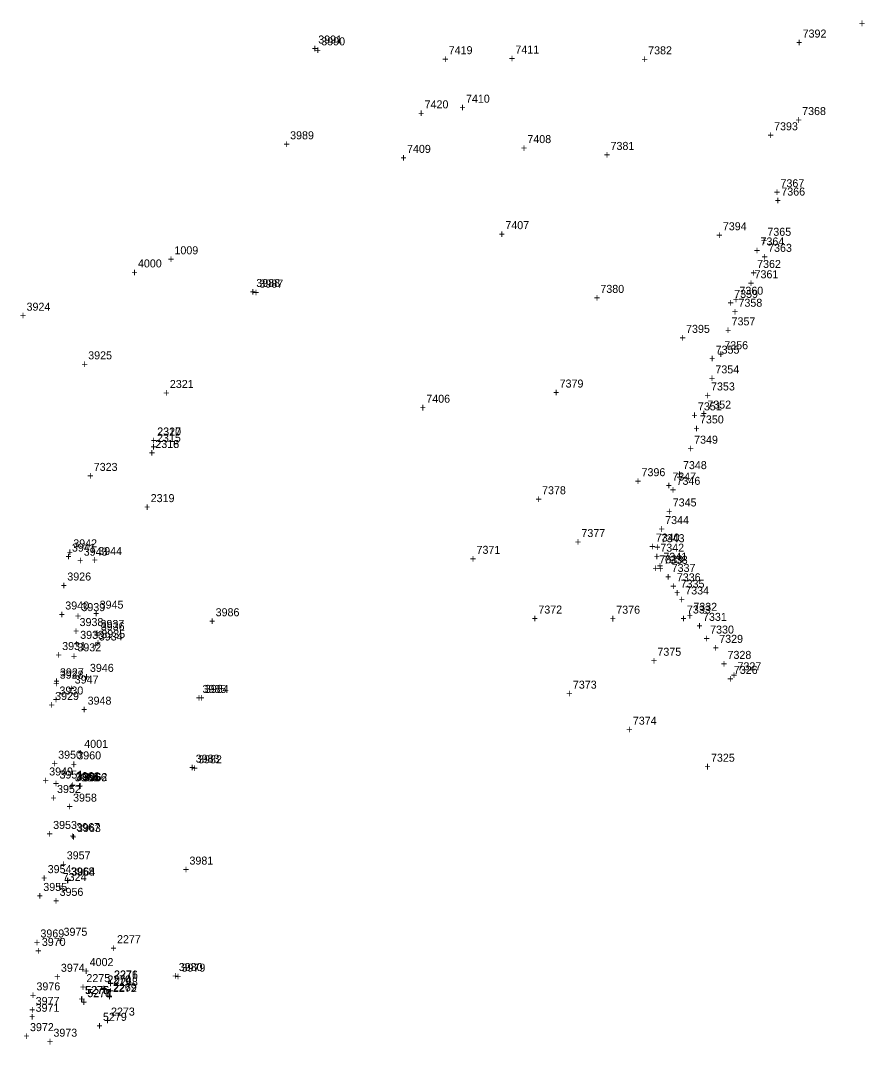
# Model space of a CAD drawing. Extents: x 1136220 to 1137808, y 528804 to 531215.
# Drawn here: x 1137418.6 to 1137682.5, y 530575 to 530894.9 of the extents above; entities that cross this region are included whole.
import ezdxf

# ---------------------------------------------------------------- set-up
doc = ezdxf.new("R2010")
doc.units = 0
for name, color, linetype in [('S_Buildings_SillElevation', 7, 'Continuous'), ('S_Drainage_CB', 7, 'Continuous'), ('S_Drainage_Culvert_Top', 7, 'Continuous'), ('S_Drainage_Invert', 7, 'Continuous'), ('S_Drainage_Sump', 7, 'Continuous'), ('S_Ground_Elevation', 7, 'Continuous'), ('S_Ground_SpotElevation', 7, 'Continuous'), ('S_Property_IronPipeFound', 7, 'Continuous'), ('S_Property_RockBoulder', 7, 'Continuous'), ('S_RetWall_Top', 7, 'Continuous'), ('S_Roadway_Monument', 7, 'Continuous'), ('S_Utilities_UG_Sanitary_MH', 7, 'Continuous'), ('S_Utilities_UG_Water_Line', 7, 'Continuous'), ('S_Utilities_UG_Water_Shutoff', 7, 'Continuous')]:
    doc.layers.add(name, color=color, linetype=linetype)

msp = doc.modelspace()

# ---------------------------------------------------------------- texts
at = {"layer": 'S_Buildings_SillElevation'}
for s, p in [('3924', (1137420.51, 530804.24)), ('+', (1137418.45, 530801.49)), ('3925', (1137439.79, 530789.05)), ('+', (1137437.72, 530786.3)), ('3926', (1137433.26, 530719.94)), ('+', (1137431.2, 530717.19)), ('3928', (1137430.89, 530689.27)), ('3927', (1137430.95, 530690.02)), ('+', (1137428.83, 530686.52)), ('+', (1137428.89, 530687.27)), ('3949', (1137427.59, 530659.04)), ('+', (1137425.53, 530656.29)), ('3976', (1137423.61, 530591.89)), ('+', (1137421.55, 530589.14)), ('3977', (1137423.37, 530587.34)), ('+', (1137421.31, 530584.59))]:
    msp.add_text(s, height=2.5, dxfattribs=at).set_placement(p)
at = {"layer": 'S_Drainage_CB'}
for s, p in [('5275', (1137438.78, 530590.73)), ('+', (1137436.72, 530587.98))]:
    msp.add_text(s, height=2.5, dxfattribs=at).set_placement(p)
at = {"layer": 'S_Drainage_Culvert_Top'}
for s, p in [('2321', (1137465.32, 530780.1)), ('+', (1137463.26, 530777.35)), ('2320', (1137461.37, 530765.23)), ('+', (1137459.31, 530762.48)), ('2318', (1137460.8, 530761.36)), ('+', (1137458.74, 530758.61)), ('2319', (1137459.32, 530744.44)), ('+', (1137457.26, 530741.69)), ('2277', (1137448.8, 530606.64)), ('+', (1137446.74, 530603.89)), ('2275', (1137439.22, 530594.47)), ('2274', (1137445.83, 530594.04)), ('2276', (1137447.9, 530595.56)), ('+', (1137437.16, 530591.72)), ('5278', (1137439.5, 530589.77)), ('+', (1137443.77, 530591.29)), ('+', (1137445.84, 530592.81)), ('2272', (1137447.52, 530591.36)), ('+', (1137437.44, 530587.02)), ('+', (1137445.45, 530588.62)), ('2273', (1137446.92, 530584.02)), ('5279', (1137444.41, 530582.38)), ('+', (1137444.86, 530581.27)), ('+', (1137442.35, 530579.63))]:
    msp.add_text(s, height=2.5, dxfattribs=at).set_placement(p)
at = {"layer": 'S_Drainage_Invert'}
for s, p in [('2317', (1137461.37, 530765.26)), ('+', (1137459.31, 530762.51)), ('2316', (1137460.77, 530761.36)), ('+', (1137458.71, 530758.61)), ('2271', (1137447.84, 530595.63)), ('2270', (1137445.77, 530594.05)), ('+', (1137445.78, 530592.88)), ('5277', (1137439.53, 530589.82)), ('+', (1137443.71, 530591.3)), ('2269', (1137447.53, 530591.62)), ('+', (1137437.47, 530587.07)), ('+', (1137445.47, 530588.87))]:
    msp.add_text(s, height=2.5, dxfattribs=at).set_placement(p)
at = {"layer": 'S_Drainage_Sump'}
for s, p in [('1009', (1137466.75, 530821.87)), ('+', (1137464.69, 530819.12)), ('5276', (1137438.93, 530590.76)), ('+', (1137436.87, 530588.01))]:
    msp.add_text(s, height=2.5, dxfattribs=at).set_placement(p)
at = {"layer": 'S_Ground_Elevation'}
for s, p in [('+', (1137680.71, 530892.82)), ('7392', (1137663.14, 530889.58)), ('7419', (1137552.5, 530884.39)), ('7411', (1137573.35, 530884.6)), ('7382', (1137614.85, 530884.34)), ('+', (1137661.07, 530886.83)), ('+', (1137550.44, 530881.64)), ('+', (1137571.29, 530881.85)), ('+', (1137612.78, 530881.59)), ('7410', (1137557.89, 530869.23)), ('7420', (1137544.96, 530867.47)), ('+', (1137555.83, 530866.48)), ('7368', (1137662.99, 530865.37)), ('+', (1137542.9, 530864.72)), ('+', (1137660.93, 530862.62)), ('7393', (1137654.22, 530860.62)), ('7408', (1137577.09, 530856.61)), ('+', (1137652.16, 530857.87)), ('7409', (1137539.46, 530853.55)), ('+', (1137575.03, 530853.86)), ('7381', (1137603.09, 530854.48)), ('+', (1137537.4, 530850.8)), ('+', (1137601.03, 530851.73)), ('7367', (1137656.22, 530842.81)), ('+', (1137654.16, 530840.06)), ('7407', (1137570.2, 530829.72)), ('7394', (1137638.2, 530829.37)), ('+', (1137568.14, 530826.97)), ('+', (1137636.14, 530826.62)), ('7364', (1137649.97, 530824.62)), ('+', (1137647.91, 530821.87)), ('7380', (1137599.91, 530809.81)), ('7359', (1137641.75, 530808.24)), ('+', (1137597.85, 530807.06)), ('+', (1137639.69, 530805.49)), ('7395', (1137626.7, 530797.32)), ('+', (1137624.64, 530794.57)), ('7355', (1137635.94, 530790.82)), ('+', (1137633.87, 530788.07)), ('7379', (1137587.17, 530780.23)), ('7406', (1137545.49, 530775.49)), ('+', (1137585.11, 530777.48)), ('+', (1137543.42, 530772.74)), ('7351', (1137630.41, 530773.11)), ('+', (1137628.35, 530770.36)), ('7396', (1137612.78, 530752.54)), ('+', (1137610.72, 530749.79)), ('7347', (1137622.4, 530751.18)), ('7378', (1137581.68, 530746.9)), ('+', (1137620.34, 530748.43)), ('+', (1137579.62, 530744.15)), ('7377', (1137593.98, 530733.53)), ('+', (1137591.92, 530730.78)), ('7340', (1137617.24, 530732.12)), ('3941', (1137434.7, 530728.98)), ('7371', (1137561.19, 530728.28)), ('+', (1137615.18, 530729.37)), ('+', (1137432.64, 530726.23)), ('+', (1137559.13, 530725.53)), ('7339', (1137618.31, 530725.3)), ('+', (1137616.25, 530722.55)), ('3940', (1137432.62, 530710.89)), ('+', (1137430.56, 530708.14)), ('3939', (1137437.67, 530710.38)), ('7372', (1137580.52, 530709.62)), ('7376', (1137604.88, 530709.57)), ('7333', (1137626.97, 530709.64)), ('+', (1137435.6, 530707.63)), ('3938', (1137437.09, 530705.71)), ('3937', (1137443.63, 530705.13)), ('3936', (1137443.72, 530704.4)), ('+', (1137578.46, 530706.87)), ('+', (1137602.82, 530706.82)), ('+', (1137624.91, 530706.89)), ('+', (1137435.03, 530702.96)), ('3933', (1137437.29, 530701.72)), ('+', (1137441.57, 530702.38)), ('+', (1137441.66, 530701.65)), ('3934', (1137443.11, 530701.21)), ('3935', (1137443.9, 530702)), ('3931', (1137431.65, 530698.22)), ('+', (1137435.23, 530698.97)), ('+', (1137441.05, 530698.46)), ('+', (1137441.84, 530699.25)), ('+', (1137429.59, 530695.47)), ('3932', (1137436.41, 530697.81)), ('7375', (1137617.74, 530696.43)), ('+', (1137434.35, 530695.06)), ('+', (1137615.67, 530693.68)), ('7326', (1137641.64, 530690.77)), ('7373', (1137591.31, 530686.16)), ('+', (1137639.58, 530688.02)), ('3929', (1137429.45, 530682.62)), ('3930', (1137430.8, 530684.33)), ('+', (1137589.24, 530683.41)), ('+', (1137427.39, 530679.87)), ('+', (1137428.73, 530681.58)), ('7374', (1137610.06, 530674.91)), ('+', (1137608, 530672.16)), ('3950', (1137430.4, 530664.27)), ('7325', (1137634.49, 530663.33)), ('+', (1137428.34, 530661.52)), ('+', (1137632.43, 530660.58)), ('3951', (1137430.82, 530658.07)), ('3961', (1137436, 530657.58)), ('3962', (1137438.35, 530657.29)), ('+', (1137428.76, 530655.32)), ('3952', (1137430.04, 530653.56)), ('+', (1137433.94, 530654.83)), ('+', (1137436.29, 530654.54)), ('+', (1137427.98, 530650.81)), ('3953', (1137428.83, 530642.33)), ('3963', (1137436.29, 530641.36)), ('+', (1137426.77, 530639.58)), ('+', (1137434.23, 530638.61)), ('3954', (1137427.12, 530628.52)), ('3964', (1137434.54, 530627.74)), ('+', (1137425.06, 530625.77)), ('+', (1137432.48, 530624.99)), ('3955', (1137425.75, 530622.96)), ('+', (1137423.68, 530620.21)), ('3969', (1137424.85, 530608.42)), ('+', (1137422.79, 530605.67)), ('3970', (1137425.29, 530605.78)), ('+', (1137423.23, 530603.03)), ('3971', (1137423.35, 530585.21)), ('+', (1137421.29, 530582.46)), ('3972', (1137421.6, 530579.16)), ('+', (1137419.54, 530576.41))]:
    msp.add_text(s, height=2.5, dxfattribs=at).set_placement(p)
at = {"layer": 'S_Ground_SpotElevation'}
for s, p in [('3942', (1137435.12, 530730.31)), ('+', (1137433.06, 530727.56)), ('3943', (1137438.38, 530727.71)), ('3944', (1137442.93, 530727.9)), ('+', (1137436.32, 530724.96)), ('+', (1137440.87, 530725.15)), ('3945', (1137443.37, 530711.16)), ('+', (1137441.31, 530708.41)), ('3946', (1137440.33, 530691.41)), ('3947', (1137435.57, 530687.75)), ('+', (1137438.27, 530688.66)), ('+', (1137433.51, 530685)), ('3948', (1137439.61, 530681.17)), ('+', (1137437.55, 530678.42)), ('3960', (1137436.38, 530664.06)), ('+', (1137434.32, 530661.31)), ('3959', (1137435.59, 530657.19)), ('+', (1137433.53, 530654.44)), ('3958', (1137435.06, 530650.86)), ('+', (1137433, 530648.11)), ('3957', (1137433.08, 530632.84)), ('+', (1137431.01, 530630.09)), ('3956', (1137430.84, 530621.42)), ('+', (1137428.78, 530618.67)), ('3975', (1137432.08, 530608.95)), ('+', (1137430.02, 530606.2)), ('3974', (1137431.25, 530597.7)), ('+', (1137429.19, 530594.95)), ('3973', (1137428.91, 530577.41)), ('+', (1137426.84, 530574.66))]:
    msp.add_text(s, height=2.5, dxfattribs=at).set_placement(p)
at = {"layer": 'S_Property_IronPipeFound'}
for s, p in [('7324', (1137431.83, 530626.07)), ('+', (1137429.77, 530623.32))]:
    msp.add_text(s, height=2.5, dxfattribs=at).set_placement(p)
at = {"layer": 'S_Property_RockBoulder'}
for s, p in [('7366', (1137656.48, 530840.21)), ('+', (1137654.42, 530837.46)), ('7365', (1137652.12, 530827.65)), ('+', (1137650.06, 530824.9)), ('7363', (1137652.35, 530822.64)), ('7362', (1137648.91, 530817.6)), ('+', (1137650.29, 530819.89)), ('+', (1137646.85, 530814.85)), ('7361', (1137648.11, 530814.38)), ('+', (1137646.05, 530811.63)), ('7360', (1137643.38, 530809.24)), ('+', (1137641.32, 530806.49)), ('7358', (1137643.08, 530805.48)), ('+', (1137641.02, 530802.73)), ('7357', (1137640.93, 530799.67)), ('+', (1137638.87, 530796.92)), ('7356', (1137638.65, 530792.2)), ('+', (1137636.59, 530789.46)), ('7354', (1137635.87, 530784.66)), ('+', (1137633.81, 530781.91)), ('7353', (1137634.51, 530779.33)), ('+', (1137632.45, 530776.58)), ('7352', (1137633.34, 530773.66)), ('7350', (1137631.04, 530769.03)), ('+', (1137631.28, 530770.91)), ('+', (1137628.98, 530766.28)), ('7349', (1137629.22, 530762.7)), ('+', (1137627.15, 530759.95)), ('7348', (1137625.73, 530754.75)), ('+', (1137623.67, 530752)), ('7346', (1137623.72, 530749.84)), ('+', (1137621.66, 530747.09)), ('7345', (1137622.53, 530743.09)), ('+', (1137620.46, 530740.34)), ('7344', (1137620.16, 530737.58)), ('+', (1137618.1, 530734.83)), ('7343', (1137618.78, 530731.92)), ('+', (1137616.72, 530729.17)), ('7342', (1137618.65, 530728.96)), ('+', (1137616.59, 530726.21)), ('7341', (1137619.61, 530726.1)), ('7338', (1137619.76, 530725.17)), ('+', (1137617.55, 530723.35)), ('+', (1137617.7, 530722.42)), ('7337', (1137622.2, 530722.63)), ('+', (1137620.14, 530719.88)), ('7336', (1137623.81, 530719.71)), ('7335', (1137625.01, 530717.67)), ('+', (1137621.75, 530716.96)), ('+', (1137622.95, 530714.92)), ('7334', (1137626.45, 530715.59)), ('+', (1137624.38, 530712.84)), ('7332', (1137628.97, 530710.48)), ('+', (1137626.91, 530707.73)), ('7331', (1137631.99, 530707.34)), ('+', (1137629.93, 530704.59)), ('7330', (1137634.23, 530703.37)), ('+', (1137632.17, 530700.62)), ('7329', (1137637.07, 530700.47)), ('+', (1137635.01, 530697.72)), ('7328', (1137639.66, 530695.46)), ('+', (1137637.6, 530692.71)), ('7327', (1137642.78, 530691.9)), ('+', (1137640.72, 530689.15))]:
    msp.add_text(s, height=2.5, dxfattribs=at).set_placement(p)
at = {"layer": 'S_RetWall_Top'}
for s, p in [('3965', (1137436.05, 530657.37)), ('3966', (1137438.16, 530657.18)), ('+', (1137433.99, 530654.62)), ('+', (1137436.1, 530654.43)), ('3967', (1137436.04, 530641.65)), ('+', (1137433.98, 530638.9)), ('3968', (1137434.33, 530627.79)), ('+', (1137432.27, 530625.04))]:
    msp.add_text(s, height=2.5, dxfattribs=at).set_placement(p)
at = {"layer": 'S_Roadway_Monument'}
for s, p in [('7323', (1137441.52, 530754.19)), ('+', (1137439.46, 530751.44))]:
    msp.add_text(s, height=2.5, dxfattribs=at).set_placement(p)
at = {"layer": 'S_Utilities_UG_Sanitary_MH'}
for s, p in [('2315', (1137461.3, 530763.27)), ('+', (1137459.24, 530760.52)), ('2268', (1137447.86, 530593.3)), ('+', (1137445.8, 530590.56))]:
    msp.add_text(s, height=2.5, dxfattribs=at).set_placement(p)
at = {"layer": 'S_Utilities_UG_Water_Line'}
for s, p in [('3991', (1137511.72, 530887.73)), ('3990', (1137512.66, 530887.15)), ('+', (1137509.66, 530884.98)), ('+', (1137510.6, 530884.4)), ('3989', (1137502.92, 530857.8)), ('+', (1137500.86, 530855.05)), ('3988', (1137492.34, 530811.66)), ('3987', (1137493.31, 530811.47)), ('+', (1137490.28, 530808.91)), ('+', (1137491.25, 530808.72)), ('3986', (1137479.63, 530708.78)), ('+', (1137477.57, 530706.03)), ('3985', (1137475.54, 530684.82)), ('3984', (1137476.27, 530684.84)), ('+', (1137473.48, 530682.07)), ('+', (1137474.21, 530682.09)), ('3983', (1137473.39, 530663.05)), ('3982', (1137474.15, 530662.84)), ('+', (1137471.33, 530660.3)), ('+', (1137472.09, 530660.09)), ('3981', (1137471.45, 530631.19)), ('+', (1137469.39, 530628.44)), ('3980', (1137468.1, 530597.93)), ('3979', (1137468.97, 530597.74)), ('+', (1137466.04, 530595.18)), ('+', (1137466.91, 530594.99))]:
    msp.add_text(s, height=2.5, dxfattribs=at).set_placement(p)
at = {"layer": 'S_Utilities_UG_Water_Shutoff'}
for s, p in [('4000', (1137455.34, 530817.76)), ('+', (1137453.28, 530815.01)), ('4001', (1137438.55, 530667.66)), ('+', (1137436.49, 530664.91)), ('4002', (1137440.25, 530599.48)), ('+', (1137438.19, 530596.73))]:
    msp.add_text(s, height=2.5, dxfattribs=at).set_placement(p)

doc.saveas('drawing.dxf')
